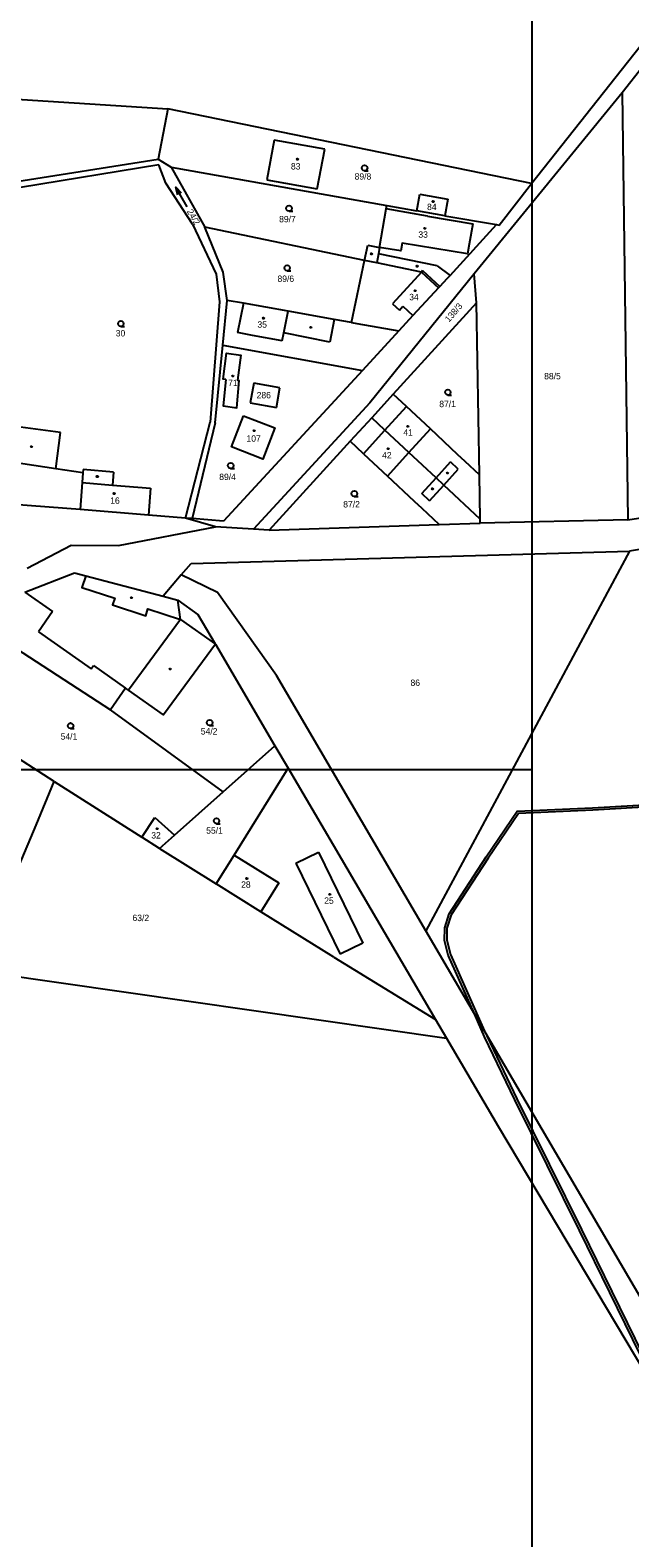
# Model space of a CAD drawing. Extents: x -752500 to -750336, y -1035826 to -1033500.
# Drawn here: x -751383.4 to -751224, y -1034704.1 to -1034303.4 of the extents above; entities that cross this region are included whole.
import ezdxf

# ---------------------------------------------------------------- set-up
doc = ezdxf.new("R2010")
doc.units = 0
for name, color, linetype in [('Default', 7, 'Continuous'), ('Hranice parcel', 7, 'Continuous'), ('ML1000', 7, 'Continuous'), ('Parcelní čísla', 7, 'Continuous'), ('Vnitřní kresba', 7, 'Continuous'), ('Věcná břemena k části', 7, 'Continuous'), ('Značky budov', 7, 'Continuous'), ('Značky kultur', 7, 'Continuous')]:
    doc.layers.add(name, color=color, linetype=linetype)

# ---------------------------------------------------------------- blocks, each defined once
blk = doc.blocks.new('304')
at = {"layer": 'Default'}
blk.add_lwpolyline([(0, 0), (-0.38, 0.1), (-0.65, 0.37), (-0.75, 0.74), (-0.65, 1.11), (-0.38, 1.38), (-0.01, 1.48), (0.36, 1.38), (0.63, 1.11), (0.73, 0.73), (0.63, 0.35), (0.36, 0.08), (-0.02, -0.02), (0.98, -0.02)], dxfattribs=at)
blk = doc.blocks.new('802')
at = {"layer": 'Default'}
blk.add_line((-3, 0), (3, 0), dxfattribs=at)
blk.add_lwpolyline([(1, 0.5), (3, 0), (1, -0.5)], dxfattribs=at)
blk = doc.blocks.new('402')
at = {"layer": 'Default'}
blk.add_lwpolyline([(0.09, 0.15), (0.18, 0), (0.09, -0.15), (-0.09, -0.15), (-0.18, 0), (-0.09, 0.15), (0.09, 0.15)], dxfattribs=at)

msp = doc.modelspace()

# ---------------------------------------------------------------- linework, layer by layer
at = {"layer": 'Hranice parcel'}
for p, q in [((-751250.21, -1034344.11), (-751179.17, -1034254.29)), ((-751176.82, -1034257.44), (-751226.06, -1034320.01)), ((-751401.38, -1034320.74), (-751346.88, -1034324.25)), ((-751226.06, -1034320.01), (-751265.43, -1034368.17)), ((-751226.06, -1034320.01), (-751224.54, -1034433.54)), ((-751346.88, -1034324.25), (-751349.38, -1034337.65)), ((-751250.21, -1034344.11), (-751346.88, -1034324.25)), ((-751318.58, -1034332.59), (-751320.52, -1034343.11)), ((-751305.12, -1034335.02), (-751318.58, -1034332.59)), ((-751307.12, -1034345.5), (-751305.12, -1034335.02)), ((-751388.63, -1034343.88), (-751349.38, -1034337.65)), ((-751349.38, -1034337.65), (-751345.97, -1034339.77)), ((-751349.22, -1034339.19), (-751386, -1034345.21)), ((-751347.37, -1034344.02), (-751349.22, -1034339.19)), ((-751345.97, -1034339.77), (-751336.97, -1034355.77)), ((-751345.97, -1034339.77), (-751288.59, -1034349.93)), ((-751320.52, -1034343.11), (-751307.12, -1034345.5)), ((-751340.29, -1034354.97), (-751347.37, -1034344.02)), ((-751280.62, -1034351.41), (-751279.88, -1034346.92)), ((-751279.88, -1034346.92), (-751272.41, -1034348.25)), ((-751258.79, -1034355.2), (-751250.21, -1034344.11)), ((-751290.57, -1034361.09), (-751288.76, -1034350.86)), ((-751288.76, -1034350.86), (-751288.59, -1034349.93)), ((-751288.59, -1034349.93), (-751280.62, -1034351.41)), ((-751272.41, -1034348.25), (-751273.19, -1034352.72)), ((-751340.29, -1034354.97), (-751334, -1034368.23)), ((-751273.19, -1034352.72), (-751280.62, -1034351.41)), ((-751273.19, -1034352.72), (-751259.44, -1034355.02)), ((-751271.8, -1034368.57), (-751259.44, -1034355.02)), ((-751259.44, -1034355.02), (-751258.79, -1034355.2)), ((-751294.56, -1034364.56), (-751336.97, -1034355.77)), ((-751332.18, -1034367.69), (-751336.97, -1034355.77)), ((-751294.56, -1034364.56), (-751293.72, -1034360.54)), ((-751293.72, -1034360.54), (-751290.57, -1034361.09)), ((-751298.02, -1034381.09), (-751294.56, -1034364.56)), ((-751291.3, -1034365.23), (-751294.56, -1034364.56)), ((-751279.4, -1034367.69), (-751291.3, -1034365.23)), ((-751334, -1034368.23), (-751333.12, -1034375.56)), ((-751331.09, -1034375.2), (-751332.18, -1034367.69)), ((-751265.43, -1034368.17), (-751293.13, -1034402.46)), ((-751279.4, -1034367.69), (-751274.9, -1034371.84)), ((-751274.57, -1034371.5), (-751272.46, -1034369.29)), ((-751272.46, -1034369.29), (-751271.8, -1034368.57)), ((-751264.81, -1034375.86), (-751265.43, -1034368.17)), ((-751332.24, -1034387.06), (-751331.09, -1034375.2)), ((-751326.76, -1034375.97), (-751331.09, -1034375.2)), ((-751274.9, -1034371.84), (-751281.69, -1034379.21)), ((-751274.9, -1034371.84), (-751274.57, -1034371.5)), ((-751333.12, -1034375.56), (-751335.62, -1034407.54)), ((-751314.88, -1034378.09), (-751326.76, -1034375.97)), ((-751302.59, -1034380.28), (-751314.88, -1034378.09)), ((-751264.81, -1034375.86), (-751286.95, -1034400.14)), ((-751281.69, -1034379.21), (-751285.48, -1034383.32)), ((-751264, -1034421.58), (-751264.81, -1034375.86)), ((-751298.02, -1034381.09), (-751302.59, -1034380.28)), ((-751298.02, -1034381.09), (-751296.63, -1034381.34)), ((-751296.63, -1034381.34), (-751285.48, -1034383.32)), ((-751334.25, -1034407.77), (-751332.24, -1034387.06)), ((-751332.24, -1034387.06), (-751295.13, -1034393.79)), ((-751285.48, -1034383.32), (-751295.13, -1034393.79)), ((-751295.13, -1034393.79), (-751332.07, -1034433.84)), ((-751323.98, -1034397.15), (-751324.94, -1034402.42)), ((-751317.05, -1034398.41), (-751323.98, -1034397.15)), ((-751318, -1034403.67), (-751317.05, -1034398.41)), ((-751324.94, -1034402.42), (-751318, -1034403.67)), ((-751293.13, -1034402.46), (-751324.07, -1034436.04)), ((-751286.95, -1034400.14), (-751292.64, -1034406.38)), ((-751283.44, -1034403.42), (-751286.95, -1034400.14)), ((-751292.64, -1034406.38), (-751298.35, -1034412.65)), ((-751289.12, -1034409.67), (-751292.64, -1034406.38)), ((-751277.06, -1034409.37), (-751283.44, -1034403.42)), ((-751375.36, -1034410.28), (-751390.04, -1034408.37)), ((-751376.63, -1034419.94), (-751375.36, -1034410.28)), ((-751342.13, -1034433.05), (-751335.62, -1034407.54)), ((-751334.25, -1034407.77), (-751340.35, -1034433.19)), ((-751282.76, -1034415.62), (-751289.12, -1034409.67)), ((-751269.84, -1034416.12), (-751277.06, -1034409.37)), ((-751224.54, -1034433.54), (-751060.39, -1034407.52)), ((-751298.35, -1034412.65), (-751319.91, -1034436.3)), ((-751294.83, -1034415.94), (-751298.35, -1034412.65)), ((-751060.35, -1034415.09), (-751224.07, -1034441.83)), ((-751294.83, -1034415.94), (-751288.47, -1034421.88)), ((-751275.54, -1034422.36), (-751282.76, -1034415.62)), ((-751267.78, -1034418.04), (-751269.84, -1034416.12)), ((-751264, -1034421.58), (-751267.78, -1034418.04)), ((-751369.45, -1034421), (-751376.63, -1034419.94)), ((-751369.39, -1034420.17), (-751369.45, -1034421)), ((-751361.26, -1034420.82), (-751369.39, -1034420.17)), ((-751361.26, -1034420.82), (-751361.54, -1034424.27)), ((-751281.25, -1034428.62), (-751288.47, -1034421.88)), ((-751273.48, -1034424.28), (-751275.54, -1034422.36)), ((-751263.79, -1034433.33), (-751264, -1034421.58)), ((-751361.54, -1034424.27), (-751351.42, -1034425.08)), ((-751351.42, -1034425.08), (-751352, -1034432.26)), ((-751263.79, -1034433.33), (-751273.48, -1034424.28)), ((-751370.18, -1034430.8), (-751392.78, -1034429.08)), ((-751352, -1034432.26), (-751370.18, -1034430.8)), ((-751279.19, -1034430.54), (-751281.25, -1034428.62)), ((-751274.67, -1034434.76), (-751279.19, -1034430.54)), ((-751342.13, -1034433.05), (-751352, -1034432.26)), ((-751340.35, -1034433.19), (-751342.13, -1034433.05)), ((-751334.17, -1034435.42), (-751342.13, -1034433.05)), ((-751332.07, -1034433.84), (-751340.35, -1034433.19)), ((-751319.91, -1034436.3), (-751274.67, -1034434.76)), ((-751274.67, -1034434.76), (-751263.77, -1034434.39)), ((-751263.77, -1034434.39), (-751263.79, -1034433.33)), ((-751224.54, -1034433.54), (-751263.77, -1034434.39)), ((-751359.96, -1034440.37), (-751334.17, -1034435.42)), ((-751324.07, -1034436.04), (-751334.17, -1034435.42)), ((-751319.91, -1034436.3), (-751324.07, -1034436.04)), ((-751384.22, -1034446.36), (-751372.58, -1034440.28)), ((-751372.58, -1034440.28), (-751359.96, -1034440.37)), ((-751340.67, -1034445.11), (-751224.07, -1034441.83)), ((-751224.07, -1034441.83), (-751278.23, -1034542.79)), ((-751343.26, -1034448.14), (-751340.67, -1034445.11)), ((-751384.87, -1034452.74), (-751371.68, -1034447.63)), ((-751371.68, -1034447.63), (-751368.66, -1034448.43)), ((-751368.66, -1034448.43), (-751348.13, -1034453.84)), ((-751343.26, -1034448.14), (-751348.13, -1034453.84)), ((-751333.6, -1034452.8), (-751343.26, -1034448.14)), ((-751348.13, -1034453.84), (-751344.2, -1034454.87)), ((-751344.2, -1034454.87), (-751338.77, -1034458.75)), ((-751317.95, -1034474.89), (-751333.6, -1034452.8)), ((-751334.18, -1034466.57), (-751338.77, -1034458.75)), ((-751396.05, -1034461.98), (-751362.12, -1034484.02)), ((-751334.18, -1034466.57), (-751318.36, -1034493.56)), ((-751278.23, -1034542.79), (-751317.95, -1034474.89)), ((-751358.06, -1034478.25), (-751362.12, -1034484.02)), ((-751357.31, -1034478.78), (-751358.06, -1034478.25)), ((-751332.1, -1034505.79), (-751362.12, -1034484.02)), ((-751377.1, -1034503.02), (-751390.83, -1034494.22)), ((-751332.1, -1034505.79), (-751318.36, -1034493.56)), ((-751318.36, -1034493.56), (-751314.87, -1034499.52)), ((-751381.87, -1034514.7), (-751377.1, -1034503.02)), ((-751377.1, -1034503.02), (-751353.74, -1034517.86)), ((-751329.25, -1034522.61), (-751314.87, -1034499.52)), ((-751314.87, -1034499.52), (-751302.9, -1034519.93)), ((-751345.07, -1034517.33), (-751332.1, -1034505.79)), ((-751386.39, -1034525.42), (-751381.87, -1034514.7)), ((-751353.74, -1034517.86), (-751350.28, -1034512.59)), ((-751350.28, -1034512.59), (-751345.07, -1034517.33)), ((-751349.09, -1034520.91), (-751353.74, -1034517.86)), ((-751349.09, -1034520.91), (-751345.07, -1034517.33)), ((-751349.09, -1034520.91), (-751334.03, -1034530.29)), ((-751334.03, -1034530.29), (-751329.25, -1034522.61)), ((-751329.25, -1034522.61), (-751317.32, -1034530.04)), ((-751302.9, -1034519.93), (-751289.24, -1034543.22)), ((-751322.1, -1034537.72), (-751334.03, -1034530.29)), ((-751317.32, -1034530.04), (-751322.1, -1034537.72)), ((-751302.76, -1034549.77), (-751322.1, -1034537.72)), ((-751289.24, -1034543.22), (-751275.68, -1034566.35)), ((-751161.12, -1034742.97), (-751278.23, -1034542.79)), ((-751302.76, -1034549.77), (-751275.68, -1034566.35)), ((-751397.73, -1034553.31), (-751272.79, -1034571.27)), ((-751275.68, -1034566.35), (-751272.79, -1034571.27)), ((-751272.79, -1034571.27), (-751258.95, -1034594.87)), ((-751258.95, -1034594.87), (-751219.84, -1034660.39))]:
    msp.add_line(p, q, dxfattribs=at)
for points in [[(-751331.46, -1034396.21), (-751332.16, -1034396.12), (-751331.28, -1034389.18), (-751327.48, -1034389.71), (-751328.31, -1034396.36), (-751327.89, -1034396.45)], [(-751331.46, -1034396.21), (-751332.1, -1034403.22), (-751328.51, -1034403.71), (-751327.89, -1034396.45)], [(-751334.18, -1034466.57), (-751347.98, -1034485.33), (-751357.31, -1034478.78)]]:
    msp.add_lwpolyline(points, dxfattribs=at)
msp.add_lwpolyline([(-751326.7, -1034405.86), (-751318.4, -1034409.09), (-751321.63, -1034417.37), (-751329.92, -1034414.14)], close=True, dxfattribs=at)
at = {"layer": 'ML1000'}
for points in [[(-751250, -1035000), (-751250, -1034500), (-751250, -1034000), (-751250, -1033500)], [(-751250, -1034500), (-751875, -1034500), (-752500, -1034500)]]:
    msp.add_lwpolyline(points, dxfattribs=at)
at = {"layer": 'Vnitřní kresba'}
for p, q in [((-751277.83, -1034352.77), (-751288.76, -1034350.86)), ((-751277.83, -1034352.77), (-751265.76, -1034354.88)), ((-751265.76, -1034354.88), (-751266.7, -1034360.25)), ((-751290.88, -1034362.85), (-751291.3, -1034365.23)), ((-751290.57, -1034361.09), (-751290.88, -1034362.85)), ((-751275.21, -1034366), (-751290.88, -1034362.85)), ((-751275.21, -1034366), (-751271.8, -1034368.57)), ((-751279.4, -1034367.69), (-751287.14, -1034376.09)), ((-751279.16, -1034367.26), (-751279.4, -1034367.69)), ((-751279.16, -1034367.26), (-751274.57, -1034371.5)), ((-751326.76, -1034375.97), (-751328.32, -1034383.76)), ((-751316.04, -1034383.82), (-751314.88, -1034378.09)), ((-751287.14, -1034376.09), (-751285.3, -1034377.79)), ((-751285.3, -1034377.79), (-751284.35, -1034376.76)), ((-751284.35, -1034376.76), (-751281.69, -1034379.21)), ((-751302.59, -1034380.28), (-751303.77, -1034386.3)), ((-751324.32, -1034384.5), (-751328.32, -1034383.76)), ((-751316.47, -1034385.94), (-751324.32, -1034384.5)), ((-751316.47, -1034385.94), (-751316.04, -1034383.82)), ((-751303.77, -1034386.3), (-751316.04, -1034383.82)), ((-751289.12, -1034409.67), (-751283.44, -1034403.42)), ((-751294.83, -1034415.94), (-751289.12, -1034409.67)), ((-751282.76, -1034415.62), (-751277.06, -1034409.37)), ((-751376.63, -1034419.94), (-751391.27, -1034417.77)), ((-751288.47, -1034421.88), (-751282.76, -1034415.62)), ((-751275.54, -1034422.36), (-751271.68, -1034418.13)), ((-751269.62, -1034420.05), (-751271.68, -1034418.13)), ((-751369.45, -1034421), (-751369.65, -1034423.62)), ((-751279.35, -1034426.54), (-751275.54, -1034422.36)), ((-751273.48, -1034424.28), (-751269.62, -1034420.05)), ((-751369.65, -1034423.62), (-751370.18, -1034430.8)), ((-751369.65, -1034423.62), (-751361.54, -1034424.27)), ((-751277.29, -1034428.46), (-751279.35, -1034426.54)), ((-751277.29, -1034428.46), (-751273.48, -1034424.28)), ((-751384.87, -1034452.74), (-751377.51, -1034457.92)), ((-751343.51, -1034460.01), (-751344.2, -1034454.87)), ((-751377.51, -1034457.92), (-751381.27, -1034463.27)), ((-751381.27, -1034463.27), (-751367.24, -1034473.14)), ((-751343.51, -1034460.01), (-751357.31, -1034478.78)), ((-751343.51, -1034460.01), (-751334.18, -1034466.57)), ((-751367.24, -1034473.14), (-751366.61, -1034472.24)), ((-751366.61, -1034472.24), (-751358.06, -1034478.25)), ((-751312.79, -1034524.74), (-751306.79, -1034521.82)), ((-751306.79, -1034521.82), (-751295.04, -1034546.03)), ((-751312.79, -1034524.74), (-751301.02, -1034548.93)), ((-751295.04, -1034546.03), (-751301.02, -1034548.93))]:
    msp.add_line(p, q, dxfattribs=at)
for points in [[(-751266.7, -1034360.25), (-751267.14, -1034362.78), (-751284.54, -1034359.99), (-751284.86, -1034362), (-751290.57, -1034361.09)], [(-751368.66, -1034448.43), (-751369.67, -1034451.51), (-751360.98, -1034454.37), (-751361.54, -1034456.08), (-751352.71, -1034458.99), (-751352.12, -1034457.18), (-751343.51, -1034460.01)]]:
    msp.add_lwpolyline(points, dxfattribs=at)
at = {"layer": 'Věcná břemena k části'}
for p, q in [((-751265.35, -1034564.81), (-751262.63, -1034569.46)), ((-751262.63, -1034569.46), (-751265.35, -1034564.81))]:
    msp.add_line(p, q, dxfattribs=at)
for points in [[(-751265.35, -1034564.81), (-751272.28, -1034549.21), (-751273.29, -1034545.3), (-751273.24, -1034541.98), (-751272.04, -1034538.21), (-751262.2, -1034523.06), (-751253.94, -1034510.95), (-751233.94, -1034510.09), (-751200.29, -1034508.13), (-751200.35, -1034508), (-751200.53, -1034508.07), (-751200.9, -1034507.14), (-751199.97, -1034506.77), (-751199.6, -1034507.7), (-751199.79, -1034507.77), (-751199.43, -1034508.69), (-751233.9, -1034510.69), (-751253.62, -1034511.53), (-751261.7, -1034523.4), (-751271.5, -1034538.47), (-751272.64, -1034542.08), (-751272.69, -1034545.22), (-751271.72, -1034549.01), (-751262.63, -1034569.46)], [(-751212.7, -1034672.42), (-751215.53, -1034666.02), (-751221.2, -1034655.54), (-751229.33, -1034638.88), (-751237.39, -1034622.42), (-751254.6, -1034587.64), (-751262.62, -1034570.95), (-751265.35, -1034564.81)], [(-751262.63, -1034569.46), (-751262.08, -1034570.69), (-751254.06, -1034587.38), (-751236.85, -1034622.16), (-751228.79, -1034638.62), (-751220.66, -1034655.26), (-751214.99, -1034665.76), (-751210.16, -1034676.7)]]:
    msp.add_lwpolyline(points, dxfattribs=at)

# ---------------------------------------------------------------- block references
at = {"layer": 'Značky budov'}
for p in [(-751312.36, -1034337.67), (-751276.35, -1034348.89), (-751278.5, -1034356.05), (-751292.68, -1034362.82), (-751280.57, -1034366.08), (-751281.07, -1034372.58), (-751321.42, -1034379.92), (-751308.86, -1034382.34), (-751329.6, -1034395.31), (-751323.86, -1034409.84), (-751283.01, -1034408.65), (-751383.13, -1034414.07), (-751288.24, -1034414.58), (-751365.59, -1034422.01), (-751272.5, -1034421.08), (-751361.15, -1034426.52), (-751276.45, -1034425.28), (-751356.52, -1034454.19), (-751346.19, -1034473.18), (-751349.66, -1034515.59), (-751325.85, -1034528.86), (-751303.78, -1034533.04)]:
    msp.add_blockref('402', p, dxfattribs=at)
at = {"layer": 'Značky kultur'}
for p in [(-751294.54, -1034340.73), (-751314.61, -1034351.47), (-751315.1, -1034367.31), (-751359.34, -1034382.12), (-751272.41, -1034400.34), (-751330.13, -1034419.84), (-751297.25, -1034427.3), (-751335.71, -1034488.16), (-751372.69, -1034488.99), (-751333.89, -1034514.28)]:
    msp.add_blockref('304', p, dxfattribs=at)
at = {"layer": 'Značky kultur', "rotation": 119.805475}
msp.add_blockref('802', (-751343.23, -1034347.73), dxfattribs=at)

# ---------------------------------------------------------------- texts
at = {"layer": 'Parcelní čísla'}
for s, p in [('83', (-751314.12, -1034340.4)), ('89/8', (-751297.19, -1034343.09)), ('84', (-751277.93, -1034351.19)), ('89/7', (-751317.25, -1034354.44)), ('33', (-751280.24, -1034358.54)), ('89/6', (-751317.7, -1034370.28)), ('34', (-751282.68, -1034375.15)), ('30', (-751360.69, -1034384.77)), ('35', (-751323.03, -1034382.44)), ('88/5', (-751246.8, -1034396.18)), ('71', (-751330.81, -1034397.96)), ('286', (-751323.24, -1034401.22)), ('87/1', (-751274.68, -1034403.57)), ('107', (-751325.94, -1034412.76)), ('41', (-751284.23, -1034411.13)), ('42', (-751289.87, -1034417.17)), ('89/4', (-751333.18, -1034422.94)), ('16', (-751362.17, -1034429.25)), ('87/2', (-751300.22, -1034430.23)), ('86', (-751282.33, -1034477.67)), ('54/1', (-751375.34, -1034491.94)), ('54/2', (-751338.08, -1034490.58)), ('55/1', (-751336.65, -1034516.93)), ('32', (-751351.25, -1034518.22)), ('28', (-751327.36, -1034531.31)), ('25', (-751305.28, -1034535.57)), ('63/2', (-751356.24, -1034540.17))]:
    msp.add_text(s, height=1.7, dxfattribs=at).set_placement(p)
for s, rotation, p in [('24/2', 300.23, (-751341.86, -1034351.53)), ('138/3', 49.332, (-751272.09, -1034381.12))]:
    msp.add_text(s, height=1.7, rotation=rotation, dxfattribs=at).set_placement(p)

doc.saveas('drawing.dxf')
